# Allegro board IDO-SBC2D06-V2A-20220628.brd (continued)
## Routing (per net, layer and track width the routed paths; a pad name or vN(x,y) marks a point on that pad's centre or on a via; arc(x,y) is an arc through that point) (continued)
LCD_PWM: length 5
  TOP w0.203: J7.29 47.96,29.11 47.7,29.37 44.44,29.37 R70.2
LCD_RSTB: length 5.3
  TOP w0.203: J7.31 48.18,28.11 47.33,28.97 45.61,28.97 45.18,28.54 R71.2
LED0/PHYAD0: length 36.4
  TOP w0.203: v1(43.15,44.79) 42.82,45.12 R61.2 42.75,46.08 42.75,47.27 42.73,47.3 U5.11 ; v1(47.01,59.4) 47.01,66.38 48.15,67.53 R38.2
  BOTTOM w0.203: v1(43.15,44.79) 44.08,43.86 44.83,43.86 45.64,44.67 46.85,44.67 50,47.81 51.43,47.81 51.99,48.37 51.99,49.59 51.07,50.51 51.07,55.33 v1(47.01,59.4)
LED3/PHYAD3: length 34
  TOP w0.203: v1(44.55,45.25) 44.52,45.22 R62.1 43.33,45.78 43.33,46.39 43.15,46.57 43.15,47.39 43.13,47.41 U5.12 ; R36.2 47.01,67.53 46.25,66.76 v1(46.25,59.4)
  BOTTOM w0.203: v1(46.25,59.4) 46.25,59.34 50.67,54.92 50.67,50.28 51.58,49.36 51.58,48.6 51.2,48.22 49.83,48.22 46.65,45.05 44.75,45.05 v1(44.55,45.25)
LINEOUTL-: length 2
  TOP w0.305: C39.2 C42.2 R80.2
LINEOUTL_: length 3.9
  TOP w0.305: C39.1 41.01,11.7 D26.1 43.55,12.79 J8.3
LINEOUTR-: length 2.3
  TOP w0.305: C40.2 C41.2 R81.2
LINEOUTR_: length 6
  TOP w0.305: C40.1 46.33,7.63 D25.1 48.26,7.68 J8.2
MDI_RN: length 3.7
  TOP w0.203: R37.1 43.55,54.14 43.47,54.06 43.47,53.83 43.67,53.63 43.96,53.63 44.52,53.07 44.52,52.25 44.33,52.06 U5.26
MDI_RP: length 3.6
  TOP w0.203: U5.27 43.93,52.12 44.19,52.39 44.19,52.94 43.83,53.3 43.54,53.3 43.14,53.7 43.14,54.06 43.06,54.14 R34.1
MDI_RXN: length 4.7
  TOP w0.203: R37.2 43.49,55.47 43.49,55.91 D20.2 43.49,56.54 43.49,56.99 43.03,57.45 43.03,57.83 43.37,58.17 U4.12
MDI_RXP: length 4.7
  TOP w0.203: R34.2 43.16,55.47 43.16,55.91 D20.1 42.85,56.25 43.16,56.57 43.16,56.86 42.7,57.32 42.7,57.86 42.37,58.2 U4.11
MDI_TN: length 4.2
  TOP w0.203: U5.29 43.13,52.02 43.06,52.09 43.06,52.55 42.31,53.3 41.4,53.3 41.24,53.45 41.24,53.94 41.45,54.14 R33.1
MDI_TP: length 4.2
  TOP w0.203: R30.1 40.71,54.14 40.91,53.94 40.91,53.32 41.26,52.97 42.17,52.97 42.73,52.42 U5.30
MDI_TXN: length 5
  TOP w0.203: R33.2 41.21,55.47 41.21,55.91 D19.2 41.21,56.54 41.21,56.78 40.67,57.31 40.54,57.31 40.03,57.83 40.03,57.99 40.37,58.32 U4.9
MDI_TXP: length 5
  TOP w0.203: U4.8 39.37,58.32 39.7,57.99 39.7,57.69 40.41,56.98 40.53,56.98 40.88,56.64 40.88,56.57 40.56,56.25 D19.1 40.88,55.91 40.88,55.47 R30.2
NSD_CD: length 10.1
  BOTTOM w0.203: R17.2 33.75,44.39 35.17,44.39 35.5,44.71 R9.2 35.5,45.51 35.94,45.95 37.09,45.95 37.97,45.08 D12.1 38.56,44.45 J4.9
PANEL_B3: length 40.8
  TOP w0.203: v1(38.72,10.8) 38.5,10.58 38.08,10.58 37.92,10.74 37.92,11.03 R64.8 ; J7.16 49.55,35.61 49.88,35.95 50.07,35.95 v1(50.28,35.74)
  BOTTOM w0.203: v1(38.72,10.8) 38.48,10.56 38.28,10.56 37.94,10.89 37.94,15 36.64,16.3 36.64,16.72 36.85,16.92 37.54,16.92 37.74,17.13 37.74,17.53 37.54,17.74 36.85,17.74 36.64,17.94 36.64,24.32 39.79,27.47 43.87,27.47 45.45,29.04 47.04,29.04 48.29,30.3 48.29,31.89 48.68,32.28 48.68,34.9 49.73,35.95 50.07,35.95 v1(50.28,35.74)
PANEL_B4: length 41
  TOP w0.203: v1(50.96,35.41) 50.73,35.17 49.64,35.17 49.58,35.11 J7.17 ; R66.5 45.04,17.58 46.63,15.98 46.63,15.33 46.5,15.2 45.65,15.2 44.43,16.42 43.57,16.42 43.22,16.07 43.22,14.85 v1(42.93,14.57)
  BOTTOM w0.203: v1(42.93,14.57) 43.25,14.89 43.25,15.54 43.65,15.93 45.91,15.93 46.12,16.14 46.12,16.54 45.91,16.75 43.65,16.75 43.25,17.14 43.25,18.42 47.77,22.94 47.77,26.25 49,27.48 49,30.16 49,31.54 49.39,31.94 49.39,34.63 49.94,35.17 50.73,35.17 v1(50.96,35.41)
PANEL_B5: length 41.1
  TOP w0.203: v1(50.96,34.61) 50.73,34.84 49.78,34.84 49.55,34.61 J7.18 ; R66.6 44.95,18.13 46.96,16.12 46.96,15.19 46.64,14.87 45.51,14.87 44.29,16.09 43.71,16.09 43.55,15.93 43.55,14.85 v1(43.84,14.57)
  BOTTOM w0.203: v1(43.84,14.57) 43.58,14.82 43.58,15.4 43.78,15.6 46.05,15.6 46.45,16 46.45,16.68 46.05,17.08 43.78,17.08 43.58,17.28 43.58,18.29 48.1,22.81 48.1,26.11 49.33,27.34 49.33,30.3 49.33,31.4 49.72,31.8 49.72,34.49 50.07,34.84 50.73,34.84 v1(50.96,34.61)
PANEL_B6: length 40.6
  TOP w0.203: v1(45.99,18.46) 45.72,18.74 44.98,18.74 44.87,18.63 R66.7 ; v1(50.28,34.26) 50.04,34.03 49.59,34.03 49.51,34.11 J7.19
  BOTTOM w0.203: v1(50.28,34.26) 50.51,34.03 51.68,34.03 52.17,33.54 52.17,32.77 50.37,30.97 50.37,29.26 51.06,28.57 52.82,28.57 53.23,28.16 53.23,26.89 52.9,26.56 50.02,26.56 49.14,25.68 49.14,24.08 50.75,22.47 50.75,21.91 50.34,21.5 49.78,21.5 49.19,22.09 48.9,22.09 48.7,21.89 48.7,21.6 50.26,20.04 50.26,19.6 49.73,19.06 49.25,19.06 47.77,20.54 47.35,20.54 47.21,20.4 47.21,20.04 48.36,18.89 48.36,17.44 47.95,17.03 47.38,17.03 46.95,17.46 46.95,18.26 46.54,18.68 46.21,18.68 v1(45.99,18.46)
PANEL_B7: length 39.5
  TOP w0.203: J7.20 49.51,33.61 49.59,33.7 50.04,33.7 v1(50.28,33.46) ; R66.8 44.81,19.18 44.92,19.07 45.8,19.07 v1(45.99,19.27)
  BOTTOM w0.203: v1(50.28,33.46) 50.51,33.7 51.54,33.7 51.84,33.4 51.84,32.91 50.04,31.11 50.04,29.12 50.92,28.24 52.69,28.24 52.9,28.02 52.9,27.02 52.77,26.89 49.88,26.89 48.81,25.82 48.81,23.94 50.42,22.33 50.42,22.04 50.21,21.83 49.92,21.83 49.33,22.42 48.76,22.42 48.37,22.02 48.37,21.46 49.93,19.9 49.93,19.73 49.59,19.39 49.38,19.39 47.91,20.87 47.21,20.87 46.88,20.54 46.88,19.9 48.03,18.76 48.03,17.57 47.81,17.36 47.52,17.36 47.29,17.59 47.29,18.4 46.67,19.01 46.25,19.01 v1(45.99,19.27)
PANEL_DCLK: length 7.7
  TOP w0.203: R72.2 C38.2 44.37,30.7 v1(45.11,29.96) ; v1(47.63,32.87) 47.89,32.61 J7.22
  BOTTOM w0.203: v1(47.63,32.87) 45.11,30.36 v1(45.11,29.96)
PANEL_DE: length 8
  TOP w0.203: J7.27 47.28,30.11 45.77,31.63 45.77,33.4 45.74,33.43 45.74,33.67 R69.2
PANEL_G2: length 39.3
  TOP w0.203: R65.6 32.92,10 v1(32.91,9.99) ; J7.9 48.06,39.11 v1(45.36,36.41)
  BOTTOM w0.203: v1(32.91,9.99) 32.91,10.5 32.68,10.73 32.68,14.59 33.29,15.2 33.29,15.26 33.32,15.29 33.32,25.64 39.9,32.22 42.95,32.22 45.36,34.63 v1(45.36,36.41)
PANEL_G3: length 43
  TOP w0.203: R65.7 33.42,10.8 33.87,10.35 34.56,10.35 v1(34.77,10.14) ; J7.10 49.51,38.61 49.59,38.53 50.04,38.53 v1(50.28,38.76)
  BOTTOM w0.203: v1(34.77,10.14) 34.55,10.35 34.18,10.35 33.78,10.76 33.78,11.58 34.23,12.03 34.23,25.32 38.79,29.88 42.77,29.88 43.03,30.13 43.03,31.22 46.27,34.46 46.27,36.53 47.23,37.49 47.86,37.49 48.9,38.53 50.04,38.53 v1(50.28,38.76)
PANEL_G4: length 43.2
  TOP w0.203: v1(50.28,37.99) 50.07,38.2 49.59,38.2 49.51,38.11 J7.11 ; R65.8 33.85,11.03 33.85,10.83 34.01,10.68 34.5,10.68 v1(34.77,10.94)
  BOTTOM w0.203: v1(34.77,10.94) 34.51,10.68 34.32,10.68 34.11,10.89 34.11,11.44 34.76,12.1 35.52,12.1 35.71,12.28 35.71,12.66 35.46,12.91 34.76,12.91 34.56,13.11 34.56,25.18 38.93,29.55 42.91,29.55 43.36,30 43.36,31.08 46.6,34.32 46.6,36.39 47.36,37.16 48,37.16 49.04,38.2 50.07,38.2 v1(50.28,37.99)
PANEL_G5: length 41.1
  TOP w0.203: v1(36.3,10.24) 36.54,10.48 36.54,10.84 36.43,10.95 R64.5 ; J7.12 49.57,37.61 49.79,37.39 50.73,37.39 v1(50.96,37.63)
  BOTTOM w0.203: v1(50.96,37.63) 50.73,37.39 49.24,37.39 47.31,35.47 47.31,34.03 44.07,30.79 44.07,29.7 43.21,28.84 39.22,28.84 35.27,24.89 35.27,14.49 36.54,13.22 36.54,10.48 v1(36.3,10.24)
PANEL_G6: length 40.4
  TOP w0.203: R64.6 36.98,10.86 36.87,10.75 36.87,10.48 v1(37.11,10.24) ; v1(50.96,36.82) 50.73,37.06 49.66,37.06 49.61,37.11 J7.13
  BOTTOM w0.203: v1(50.96,36.82) 50.73,37.06 49.37,37.06 47.64,35.33 47.64,33.89 44.4,30.65 44.4,29.56 43.34,28.51 39.36,28.51 35.6,24.75 35.6,14.63 36.87,13.36 36.87,10.48 v1(37.11,10.24)
PANEL_G7: length 40.7
  TOP w0.203: J7.14 49.55,36.61 49.88,36.28 50.07,36.28 v1(50.28,36.49) ; v1(38.72,9.99) 38.47,10.25 37.94,10.25 37.59,10.6 37.59,10.74 37.48,10.85 R64.7
  BOTTOM w0.203: v1(38.72,9.99) 38.48,10.23 38.14,10.23 37.61,10.76 37.61,14.86 36.31,16.16 36.31,24.46 39.65,27.8 43.73,27.8 45.31,29.37 46.9,29.37 47.96,30.43 47.96,32.02 48.35,32.42 48.35,35.03 49.6,36.28 50.07,36.28 v1(50.28,36.49)
PANEL_HS: length 7.8
  TOP w0.203: R67.2 44.47,32.98 44.85,32.6 44.85,31.08 45.86,30.07 v1(45.86,29.96) ; v1(47.25,31.61) J7.24
  BOTTOM w0.203: v1(47.25,31.61) 47.23,31.61 45.86,30.25 v1(45.86,29.96)
PANEL_R3: length 45.1
  TOP w0.203: R63.5 26.53,10.46 v1(26.31,10.25) ; J7.3 47,42.11 44.85,39.97 v1(44.6,39.97)
  BOTTOM w0.203: v1(44.6,39.97) 42.82,38.19 42.82,35.27 41.83,34.28 38.97,34.28 26.44,21.75 26.44,10.38 v1(26.31,10.25)
PANEL_R4: length 45.1
  TOP w0.203: J7.4 47.13,41.61 v1(44.6,39.08) ; v1(26.94,9.74) 27.08,9.87 R63.6
  BOTTOM w0.203: v1(26.94,9.74) 26.94,21.68 39.14,33.87 42,33.87 43.3,35.18 43.3,37.78 v1(44.6,39.08)
PANEL_R5: length 43.2
  TOP w0.203: R63.7 27.58,10.38 v1(27.71,10.25) ; J7.5 47.52,41.11 v1(44.6,38.19)
  BOTTOM w0.203: v1(27.71,10.25) 27.45,10.5 27.45,21.56 39.33,33.44 42.14,33.44 43.71,35.01 43.71,37.3 v1(44.6,38.19)
PANEL_R6: length 44.2
  TOP w0.203: v1(28.09,9.49) 28.34,9.74 28.34,10.5 28.13,10.72 R63.8 ; J7.6 47.85,40.61 v1(44.57,37.33)
  BOTTOM w0.203: v1(44.57,37.33) 44.22,36.98 44.22,34.89 42.36,33.03 39.5,33.03 27.96,21.49 27.96,10.88 28.34,10.5 28.34,9.74 v1(28.09,9.49)
PANEL_R7: length 39.6
  TOP w0.203: J7.7 48.17,40.11 v1(45.36,37.3) ; v1(32.15,10.38) 32.37,10.59 R65.5
  BOTTOM w0.203: v1(45.36,37.3) 44.72,36.66 44.72,34.76 42.59,32.63 39.67,32.63 32.91,25.87 32.91,15.46 32.28,14.82 32.28,10.5 v1(32.15,10.38)
PANEL_VS: length 8.2
  TOP w0.203: v1(46.62,29.95) 46.62,30.03 45.36,31.28 45.36,33.24 44.47,34.12 R68.2 ; v1(47.37,30.85) 47.63,31.11 J7.25
  BOTTOM w0.203: v1(47.37,30.85) 46.62,30.1 v1(46.62,29.95)
PHY_AVDD33: length 0.7
  TOP w0.203: 42.18,52.29 42.33,52.14 U5.31
  vias: v1(38.88,53.43) v1(39.64,53.43) v1(44.72,53.94) v1(45.49,53.94)
PHY_DVDD33: length 26.9
  TOP w0.203: R55.1 37.94,47.43 38.79,46.58 40.77,46.58 41.44,45.91 41.44,45.64 43.68,43.4 46.25,43.4 46.63,43.78 46.63,45.17 v1(46.12,45.68) ; 44.08,46.18 43.53,46.73 U5.13
  TOP w0.381: 44.08,46.18 44.32,45.94 45.11,45.94 45.33,45.71 C32.2
  TOP w0.508: R59.1 v1(48.59,50) ; C32.2 45.66,45.22 46.12,45.68 v1(46.12,45.68) ; R60.1 v1(48.59,52.29)
  BOTTOM w0.508: v1(48.59,52.29) v1(48.59,50) ; 49.42,50 49.42,48.61 46.5,45.68 v1(46.12,45.68)
  vias: v1(48.66,53.94) v1(49.42,53.94)
PM_IRIN: length 53.5
  TOP w0.203: U2.23 12.96,17.84 13.66,18.53 18.21,18.53 19.92,20.24 19.92,25.17 16.43,28.66 16.43,33.15 v1(16.25,33.33)
  BOTTOM w0.203: 4.85,54.19 4.85,53.17 3.42,51.75 3.42,45.77 3.74,45.45 3.74,43.64 4.51,42.86 5,42.86 5.94,41.92 5.94,40.8 6.22,40.53 6.22,39.04 9.49,35.76 10.95,35.76 13.1,33.62 15.97,33.62 v1(16.25,33.33)
PM_LED0: length 32
  TOP w0.203: R31.1 28.72,62.95 30.88,60.79 v1(30.88,55.97) ; U2.78 33.48,44.55 32.23,45.8 32.23,50.27 33,51.04 34.54,51.04 35.39,51.88 35.71,51.88 36.16,52.34 v1(36.16,52.59)
  BOTTOM w0.203: v1(36.16,52.59) 36.16,52.72 35.83,53.05 32.85,53.05 30.88,55.02 v1(30.88,55.97)
PM_LED0_: length 22.1
  TOP w0.203: v1(29.61,62.95) 29.61,68.54 29.18,68.97 R31.2
  BOTTOM w0.203: J6.B12 38.12,71.35 38.12,68.29 32.79,62.95 v1(29.61,62.95)
PM_LED1: length 31.3
  TOP w0.203: v1(35.39,52.46) 34.38,51.45 32.83,51.45 31.77,50.39 31.77,45.47 32.38,44.86 U2.79 ; R29.1 28.21,67.48 28.21,62.83 30.25,60.79 v1(30.25,56.48)
  BOTTOM w0.203: v1(35.39,52.46) 35.21,52.64 32.68,52.64 30.25,55.08 v1(30.25,56.48)
PM_LED1_: length 4.4
  TOP w0.203: J6.B10 27.58,70.46 R29.2
PM_RESET: length 43.8
  TOP w0.203: SW1.3 42.84,4 41.17,5.68 D3.1 40.89,6.59 40.53,6.95 40.53,7.8 40.28,8.06 39.33,8.06 38.96,8.42 31.06,8.42 v1(30.88,8.6) ; U2.24 12.52,16.74 13.9,18.13 16.91,18.13 v1(17.81,17.23)
  BOTTOM w0.203: v1(17.81,17.23) 17.86,17.23 23,12.09 23.44,12.09 24.98,10.55 24.98,9.03 26.02,8 30.28,8 v1(30.88,8.6)
PM_UART_RX: length 43
  TOP w0.203: v1(23.9,10.76) 23.9,10.38 26.97,7.3 26.97,2.41 26.17,1.61 17.67,1.61 14.74,4.55 13.12,4.55 12.85,4.28 12.85,2.25 11.99,1.39 J11.4 ; U2.25 13.68,15.65 14.63,16.6 v1(15.9,16.6)
  BOTTOM w0.203: v1(15.9,16.6) 17.92,16.6 22.87,11.65 23.31,11.65 23.9,11.06 v1(23.9,10.76)
PM_UART_TX: length 38.5
  TOP w0.203: J11.3 11.86,4.18 12.64,4.96 14.96,4.96 17.93,1.99 25.8,1.99 26.56,2.76 26.56,7.07 23.13,10.5 v1(23.13,10.76) ; v1(15.26,15.96) 15.01,15.96 14.78,15.73 U2.26
  BOTTOM w0.203: v1(23.13,10.76) 17.93,15.96 v1(15.26,15.96)
REGOUT: length 2
  TOP w0.203: v1(43.63,52.69) 43.53,52.59 U5.28
  BOTTOM w0.508: v1(43.63,52.69) 43.66,52.72 R42.1
RMII_COL: length 4.1
  TOP w0.203: U5.4 40.66,49.82 40.66,49.81 40.15,49.81 39.73,49.4 39.73,49.06 39.32,48.65 39.32,48.1 38.8,47.59 R55.2
RMII_MDC: length 2.2
  TOP w0.203: U5.22 45.88,50.22 46.25,50.58 46.55,50.58 47.09,51.12 R41.2
RMII_MDIO: length 3.8
  TOP w0.203: U5.23 45.75,50.62 46.25,51.12 46.25,51.19 47.09,52.03 R60.2 R40.2
RMII_REF_CLK: length 37
  TOP w0.203: v1(45.61,47.56) 45.61,47.49 46.55,46.55 R52.1
  BOTTOM w0.203: R47.2 32.02,30.06 31.49,30.59 31.49,31.67 28.5,34.67 28.5,39.87 27.81,40.56 27.81,42.99 31.77,46.95 34.35,46.95 35.21,47.81 38.33,47.81 39.17,46.97 40.07,46.97 40.25,47.15 40.66,47.15 41.46,47.95 45.22,47.95 v1(45.61,47.56)
RMII_RST: length 7.1
  TOP w0.203: U5.32 39.68,51.62 39.39,51.9 C36.2 R57.2 38.8,50.73 38.29,50.22 37.49,50.22 37.36,50.35 36.93,50.35 R51.2
RMII_RX_D0: length 2.6
  TOP w0.203: U5.18 45.97,48.62 47.01,47.59 R44.2
RMII_RX_D1: length 3.2
  TOP w0.203: R45.2 47.75,46.49 47.35,46.89 47.07,46.89 45.74,48.22 U5.17
RMII_RX_DV: length 5.3
  TOP w0.203: U5.19 46.93,49.02 R58.2 47.09,48.4 47.34,48.15 49.22,48.15 49.5,48.43 R43.2
RMII_TX_D0: length 55.6
  TOP w0.203: v1(44.79,25.04) 44.47,24.73 R48.2 ; U5.9 40.54,47.62 v1(40.41,47.75) ; v1(27.92,39.59) 29.1,38.4 29.1,29.86 34.49,24.47 38.21,24.47 v1(38.43,24.25)
  BOTTOM w0.203: v1(44.79,25.04) 44.59,25.04 44.13,24.59 40.46,24.59 40.35,24.48 39.69,24.48 39.3,24.09 38.59,24.09 v1(38.43,24.25) ; v1(40.41,47.75) 40.41,47.76 39.42,48.74 39.42,49.71 37.63,51.51 37.07,51.51 36.51,50.95 32.66,50.95 30.04,48.33 30.04,46.56 26.62,43.14 26.62,40.88 v1(27.92,39.59)
RMII_TX_D1: length 56.1
  TOP w0.203: v1(27.86,38.83) 28.7,37.99 28.7,29.69 34.7,23.68 v1(37.93,23.68) ; R49.2 44.52,23.58 v1(44.78,23.84) ; v1(40.48,48.5) 40.77,48.22 U5.8
  BOTTOM w0.203: v1(40.48,48.5) 39.83,49.15 39.83,49.88 37.79,51.92 36.9,51.92 36.34,51.36 32.49,51.36 29.64,48.5 29.64,46.73 26.21,43.31 26.21,40.47 v1(27.86,38.83) ; v1(44.78,23.84) 44.71,23.77 40.8,23.77 40.2,23.18 38.44,23.18 v1(37.93,23.68)
RMII_TX_EN: length 58.2
  TOP w0.203: R50.2 v1(44.78,25.87) ; v1(40.55,49.26) 40.71,49.42 U5.5 ; v1(39.06,24.67) 39.06,23.99 38.17,23.1 34.71,23.1 28.21,29.6 28.21,37.65 v1(27.83,38.03)
  BOTTOM w0.203: v1(44.78,25.87) 44.78,25.85 43.92,24.99 40.29,24.99 40.18,24.88 39.27,24.88 v1(39.06,24.67) ; v1(40.55,49.26) 40.24,49.57 40.24,50.05 37.96,52.32 36.73,52.32 36.17,51.76 32.32,51.76 29.23,48.67 29.23,46.9 25.81,43.47 25.81,40.06 v1(27.83,38.03)
RST#: length 5.9
  TOP w0.203: J7.33 46.88,27.11 D22.1 46.86,27.29 45.95,28.2 R73.2 44.95,27.42 R79.2
RTC_VBAT: length 19.2
  TOP w0.508: J2.1 26.06,58.79 26.06,53.3 24.76,52.01 v1(16.94,52.01) ; D5.A v1(16.78,49.24)
  BOTTOM w0.508: v1(16.78,49.24) 16.94,49.39 v1(16.94,52.01)
SAR_GPIO2: length 44.6
  TOP w0.203: v1(15.53,32.99) 16.02,32.5 16.02,28.49 19.51,25 19.51,20.47 17.98,18.94 U2.22
  BOTTOM w0.203: v1(15.53,32.99) 13.09,32.99 10.82,35.27 9.41,35.27 5.81,38.87 5.81,39.89 5.35,40.35 4.34,40.35 3.83,40.86 3.83,42.97 3.33,43.47 3.33,45.29 2.31,46.31 2.31,46.57
SD_CDZ: length 22.6
  TOP w0.203: U2.67 39.72,36.54 38.62,35.44 38.62,34.49 37.37,33.24 v1(33.42,33.24)
  BOTTOM w0.203: v1(33.42,33.24) 32.8,33.24 30.53,35.51 30.53,42.12 32.26,43.85 R17.1
SD_CLK: length 14.5
  TOP w0.203: v1(32.69,36.69) 34.07,36.69 34.4,36.36 34.92,36.36 36.12,37.55 38.12,37.55 40.41,39.84 U2.70
  BOTTOM w0.203: R18.1 32.36,37.03 v1(32.69,36.69)
SD_CLK_: length 10.4
  BOTTOM w0.203: J4.5 38.9,40.05 D13.1 37.97,40.57 37.68,40.28 36.02,40.28 35.75,40.56 35.75,40.86 C14.2 35.42,41.02 35.42,40.73 35.1,40.41 33.83,40.41 33.22,41.03 R18.2
SD_CMD: length 8.9
  TOP w0.203: U2.71 40.65,40.94 37.99,38.29 35.99,38.29 v1(34.64,36.94)
  BOTTOM w0.203: R16.1 v1(34.64,36.94)
SD_CMD_: length 8.1
  BOTTOM w0.203: R16.2 R8.2 35.73,37.91 37.51,37.91 37.97,37.45 D11.1 39.44,37.22 40.07,37.85 J4.3
SD_D0: length 17.6
  TOP w0.203: U2.69 40.2,38.74 36.72,35.27 v1(32.66,35.27)
  BOTTOM w0.203: R10.1 31.75,41.77 31.75,36.18 v1(32.66,35.27)
SD_D0_: length 9.8
  BOTTOM w0.203: R10.2 33.52,42.38 34.15,43.01 35.2,43.01 35.5,42.71 R7.2 35.5,42.21 36.03,41.68 37.68,41.68 37.97,41.97 D7.1 39.01,42.38 39.14,42.25 J4.7
SD_D1: length 23.3
  TOP w0.203: U2.68 39.96,37.64 38.01,35.69 38.01,34.74 37.15,33.88 v1(32.98,33.88)
  BOTTOM w0.203: R11.1 33.93,43.65 33.26,42.99 32.08,42.99 31.14,42.05 31.14,35.77 32.98,33.92 v1(32.98,33.88)
SD_D1_: length 6.7
  BOTTOM w0.203: J4.8 40.33,43.35 40.03,43.65 D8.1 37.97,43.93 37.61,44.28 36.14,44.28 R11.2
SD_D2: length 15
  TOP w0.203: v1(33.17,38.32) 33.17,38.52 35.2,40.54 35.2,41.29 35.65,41.74 37.87,41.74 38.98,42.86 U2.73
  BOTTOM w0.203: R13.1 34.5,33.49 33.27,34.71 33.27,38.23 v1(33.17,38.32)
SD_D2_: length 7.2
  BOTTOM w0.203: J4.1 40.28,35.65 40.03,35.9 39.08,35.9 37.84,34.66 D9.1 37.84,34.22 37.1,33.49 R13.2
SD_D3: length 12.8
  TOP w0.203: U2.72 39.94,42.04 38.12,40.22 35.76,40.22 33.93,38.38 v1(33.93,38.34)
  BOTTOM w0.203: v1(33.93,38.34) 33.88,38.3 33.88,35.39 R15.1
SD_D3_: length 7
  BOTTOM w0.203: R15.2 35.5,34.89 36,35.39 37.49,35.39 37.97,35.87 D10.1 38.25,36.16 38.63,36.54 39.9,36.54 40.11,36.75 J4.2
SOM_3V3: length 3.3
  TOP w0.508: C10.2 C9.2 13.17,49.25 13.17,50.97 L2.2
SYS_3V3: length 145.7
  TOP w0.254: J6.A12 48.92,68.68 48.92,67.14 47.65,65.87 47.65,56.86
  TOP w0.305: J7.38 49.82,24.61 v1(50.19,24.98)
  TOP w0.381: R61.1 41.96,46.06 40.94,47.08 40.15,47.08 v1(39.64,47.59) ; 18.31,50 18.31,48.6 17.51,47.8 D4.A ; v1(37.31,50.93) 37.78,50.93 R57.1 ; v1(17.04,56.98) 17.04,60.03 10.94,66.13 R89.1 ; C4.2 R3.1 18.61,11.69 17.42,10.5 11.9,10.5 C5.2
  TOP w0.508: v1(29.87,30.71) 29.87,31.35 30.88,32.37 30.88,36.41 32.06,37.59 34.21,37.59 v1(34.97,38.34) ; R73.1 46.9,28.41 v1(47.62,27.69) ; v1(37.57,52.9) 37.23,52.56 37.23,51.01 v1(37.31,50.93) ; v1(34,41.87) v1(29.81,41.87) 28.15,41.87 26.39,40.11 26.39,35.47 26.53,35.33 v1(26.53,32.98) ; v1(45.23,22.47) 45.92,22.47 R75.1 ; R82.1 38.5,7.84 38.88,7.45 v1(39.14,7.45) R1.1 ; v1(42.64,21.3) R74.1
  TOP w0.711: J12.1 4.85,9.41 ; J12.1 5.79,8.47 ; J12.1 3.91,8.47 ; J12.17 5.79,28.79 ; J12.17 4.85,29.73 ; J12.17 4.85,27.85
  BOTTOM w0.381: R7.1 34.13,41.87 v1(34,41.87)
  BOTTOM w0.406: v1(29.81,41.87) 29.82,41.88 29.82,42.35 32.52,45.05 R9.1
  BOTTOM w0.508: v1(17.04,56.98) 17.04,53.56 17.72,52.87 v1(17.72,51.14) ; v1(37.57,52.9) 37.57,53.39 38.88,54.7 42.44,54.7 43.07,55.33 44.85,55.33 46.25,56.73 v1(46.25,56.98) ; R8.1 34.64,38.02 v1(34.97,38.34) ; 41.8,9.87 41.7,9.97 41.7,18.52 43.2,20.03 43.2,20.74 v1(42.64,21.3) 43.81,22.47 v1(45.23,22.47) 45.69,22.47 46.76,23.53 46.76,26.83 v1(47.62,27.69) ; v1(39.64,47.59) 38.76,48.48 38.76,49.49 37.32,50.93 v1(37.31,50.93) ; 26.18,30.31 28.09,30.31 28.48,30.71 v1(29.87,30.71)
  vias: v1(8.91,8.72) v1(9.67,8.72) v1(9.89,15.05) v1(10.05,15.71) v1(10.05,9.36) v1(10.43,8.72) v1(10.69,15.33) v1(11.2,8.72) v1(11.45,15.33) v1(21.1,41.74) v1(21.1,40.98) v1(21.86,41.74) v1(21.86,40.98) v1(23.64,48.6) v1(23.64,47.84) v1(23.64,47.08) v1(23.64,46.32) v1(24.56,34.54) v1(24.56,32.06) v1(24.56,31.36) v1(50.44,25.62) v1(50.95,24.98)
TF_3V3: length 12.8
  TOP w0.508: v1(27.62,37.05) 27.1,37.56 27.1,39.82 27.6,40.32 32.85,40.32 v1(32.95,40.22)
  BOTTOM w0.508: Q1.3 26.82,37.62 C17.2 26.98,37.68 v1(27.62,37.05) ; v1(32.95,40.22) 33.53,39.63 L3.1
TP_SCL: length 10.4
  TOP w0.203: J7.36 48.12,25.61 47.87,25.36 47.87,21.8 D23.1 46.86,21.07 46.45,21.48 44.32,21.48 R74.2 R77.2
TP_SDA: length 8.3
  TOP w0.203: R76.2 44.69,21.89 46.58,21.89 46.81,22.11 R75.2 46.86,22.49 D24.1 47.46,24.19 47.46,25.53 48.05,26.11 J7.35
TTL0: length 2.8
  TOP w0.203: R63.4 26.53,12.95 25.78,13.7 U2.36
TTL1: length 2.6
  TOP w0.203: R63.3 27.07,12.15 27.07,13.3 26.88,13.49 U2.37
TTL2: length 2.7
  TOP w0.203: R63.2 27.58,12.15 27.58,13.17 27.98,13.57 U2.38
TTL3: length 2.9
  TOP w0.203: R63.1 28.13,12.83 29.08,13.78 U2.39
TTL4: length 4
  TOP w0.203: R65.4 32.37,12.57 32.15,12.79 31.14,12.79 30.18,13.75 U2.40
TTL5: length 3.6
  TOP w0.203: U2.41 31.28,13.54 31.64,13.17 32.41,13.17 32.92,12.66 R65.3
TTL6/MIPI_TX_D0P: length 2.8
  TOP w0.203: U2.43 33.48,14.01 33.86,13.62 33.86,13.23 33.53,12.89 33.53,12.54 33.42,12.43 R65.2
TTL7/MIPI_TX_D0N: length 2.8
  TOP w0.203: R65.1 33.97,12.15 33.97,12.43 33.86,12.54 33.86,12.76 34.19,13.09 34.19,13.63 34.58,14.02 U2.44
TTL8/MIPI_TX_D1P: length 2.9
  TOP w0.203: R64.4 36.43,12.43 36.54,12.54 36.54,12.78 36.06,13.26 36.06,13.62 35.68,14.01 U2.45
TTL9/MIPI_TX_D1N: length 2.9
  TOP w0.203: U2.46 36.78,14.02 36.39,13.63 36.39,13.4 36.87,12.92 36.87,12.54 36.98,12.43 R64.3
TTL10/MIPI_TX_CKP: length 3
  TOP w0.203: R64.2 37.48,12.43 37.59,12.54 37.59,12.88 38.26,13.55 38.26,13.71 37.88,14.1 U2.47
TTL11/MIPI_TX_CKN: length 3
  TOP w0.203: U2.48 38.98,14.09 38.59,13.71 38.59,13.41 37.92,12.74 37.92,12.48 38.03,12.37 38.03,12.15 R64.1
TTL12/MIPI_TX_D2P: length 2.9
  TOP w0.203: R66.4 43.34,17.58 43.23,17.69 42.89,17.69 42.33,17.13 41.95,17.13 41.57,16.74 U2.49
TTL13/MIPI_TX_D2N: length 2.9
  TOP w0.203: U2.50 41.58,17.84 41.96,17.46 42.19,17.46 42.75,18.02 43.2,18.02 43.31,18.13 R66.3
TTL14/MIPI_TX_D3P: length 3
  TOP w0.203: R66.2 43.31,18.63 43.2,18.74 42.79,18.74 42.2,19.33 41.91,19.33 41.53,18.94 U2.51
TTL15/MIPI_TX_D3N: length 3
  TOP w0.203: R66.1 43.37,19.18 43.26,19.07 42.93,19.07 42.34,19.66 41.92,19.66 41.54,20.04 U2.52
TTL16: length 44
  TOP w0.203: U2.54 40.35,22.24 39.9,22.7 34.54,22.7 25.95,31.29 25.95,35.12 25.83,35.24 25.83,40.34 27.2,41.71 v1(27.2,42) ; v1(34.82,50.29) 35.29,50.76 R51.1
  BOTTOM w0.203: v1(27.2,42) 27.2,43.14 30.45,46.39 30.45,48.17 32.57,50.29 v1(34.82,50.29)
TTL17: length 2.3
  TOP w0.203: R49.1 43.04,23.34 U2.55
TTL18: length 2.3
  TOP w0.203: U2.56 42.99,24.44 R48.1
TTL19: length 2.9
  TOP w0.203: U2.57 41.58,25.54 42.13,24.99 42.66,24.99 43.28,25.62 R50.1
TTL20: length 9.7
  TOP w0.203: v1(33.6,30.31) 36.78,27.13 40.03,27.13 40.52,26.64 U2.58
  BOTTOM w0.203: R47.1 33.35,30.06 v1(33.6,30.31)
TTL21: length 61.1
  TOP w0.203: v1(33.42,31.08) 33.93,31.08 37.26,27.74 U2.59 ; R43.1 v1(51,48.86)
  BOTTOM w0.203: v1(33.42,31.08) 32.79,31.08 28.98,34.89 28.98,40.09 28.34,40.73 28.34,42.74 32.05,46.44 34.56,46.44 35.45,47.33 37.99,47.33 38.88,46.44 40.15,46.44 40.41,46.7 40.91,46.7 41.68,47.46 44.72,47.46 45.23,46.95 45.87,46.95 47.65,48.73 47.65,54.44 47.9,54.7 49.8,54.7 50.06,54.44 50.06,49.8 v1(51,48.86)
TTL22: length 49.1
  TOP w0.203: U2.60 37.05,28.84 v1(34.18,31.71) ; R44.1 48.33,44.08 46.76,42.51 43.28,42.51 39.72,46.06 38.37,46.06 v1(37.82,46.62)
  BOTTOM w0.203: v1(34.18,31.71) 32.89,31.71 29.51,35.09 29.51,40.29 28.83,40.98 28.83,42.65 32.17,45.99 34.83,45.99 35.6,46.76 37.67,46.76 v1(37.82,46.62)
TTL23: length 44.3
  TOP w0.203: R45.1 47.77,44.28 46.48,42.99 43.55,42.99 43.3,43.24 40.72,45.82 v1(40.72,45.85) ; U2.61 36.97,29.94 v1(34.95,31.97)
  BOTTOM w0.203: v1(40.72,45.85) 37.77,45.85 37.26,46.36 35.77,46.36 35,45.59 32.34,45.59 29.23,42.48 29.23,41.15 29.92,40.46 29.92,35.26 32.83,32.35 34.56,32.35 v1(34.95,31.97)
TTL24/LCD_PCLK: length 2.5
  TOP w0.203: R72.1 42.54,31.84 41.74,31.04 U2.62
TTL25/LCD_HSYNC: length 2.5
  TOP w0.203: U2.63 41.98,32.14 42.82,32.98 R67.1
TTL26/LCD_VSYNC: length 2.6
  TOP w0.203: R68.1 42.82,34.12 41.94,33.24 U2.64
TTL27/LCD_DE: length 2.6
  TOP w0.203: U2.65 42.02,34.34 42.95,35.27 R69.1
UART0_RX: length 94.3
  TOP w0.203: v1(25.6,12.66) 25.6,9.94 27.86,7.68 27.86,2.02 26.69,0.85 17.04,0.85 16.5,1.39 J11.2 ; D30.A 3.97,66.13 R89.2 5.43,66.05 5.99,65.49 10.82,65.49 16.4,59.91 16.4,56.68 17.13,55.95 v1(17.77,55.95) ; v1(17.9,37.08) 17.98,37.08 18.5,36.56 18.5,36.07 19.27,35.3 19.27,29.83 22.76,26.35 22.76,19.77 23.52,19.02 v1(23.52,18.88)
  BOTTOM w0.203: v1(17.9,37.08) 17.72,37.25 17.72,40.66 19.17,42.11 19.17,46.99 19.48,47.3 19.48,53.08 18.74,53.82 18.74,54.56 17.77,55.53 v1(17.77,55.95) ; v1(23.52,18.88) 23.52,15.2 25.6,13.12 v1(25.6,12.66)
UART0_RX_: length 24.2
  TOP w0.203: v1(10.94,4.66) 11.81,5.52 15.54,5.52 16.94,4.13 22.14,4.13 J10.3 ; J11.6 9.86,1.42 8.4,2.88 8.4,6.57 8.56,6.72 D29.1 v1(9.04,4.66)
  BOTTOM w0.203: v1(10.94,4.66) v1(9.04,4.66)
UART0_TX: length 94.1
  TOP w0.203: v1(24.9,12.95) 24.9,10 27.45,7.45 27.45,2.19 26.5,1.23 17.29,1.23 15.13,3.39 J11.1 ; v1(18.31,56.91) 17.55,57.67 17.55,60.29 11.07,66.76 5.61,66.76 5.35,67.02 R88.1 ; v1(17.92,36.32) 17.92,36.08 18.87,35.13 18.87,29.67 22.36,26.18 22.36,19.36 v1(22.7,19.01)
  BOTTOM w0.203: v1(24.9,12.95) 24.9,13 22.94,14.96 22.94,18.78 v1(22.7,19.01) ; v1(18.31,56.91) 18.44,56.78 18.44,55.44 19.14,54.73 19.14,53.99 19.89,53.25 19.89,47.13 19.58,46.82 19.58,41.94 18.48,40.84 18.48,36.67 18.12,36.32 v1(17.92,36.32)
UART0_TX_: length 20.4
  TOP w0.203: J11.5 9.86,6.44 10.15,6.72 D28.1 10.31,6.31 10.69,5.93 15.71,5.93 17.1,4.53 23.77,4.53 J10.4
UART1_RX: length 28.8
  TOP w0.203: J12.18 2.31,28.66 3.83,27.14 3.83,23.08 4.47,22.44 5.23,22.44 6.78,20.89 6.78,15.43 8.78,13.42 17.67,13.42 18.08,13.83 U2.29
UART1_TX: length 29.2
  TOP w0.203: J12.16 3.32,25.23 3.32,22.95 3.7,22.57 3.7,20.66 4.34,20.03 5.1,20.03 5.96,19.16 5.96,14.72 8.42,12.26 13.85,12.26 14.37,12.79 18.18,12.79 19.18,13.78 U2.30
UD+: length 9.4
  TOP w0.203: 5.99,79.82 5.99,78.79 6.14,78.65 6.14,77.75 D2.1 6.06,77.15 6.16,77.05 6.16,73.53 5.92,73.29 5.29,73.29 5.14,73.44 5.14,73.66 5.21,73.73 U6.1
UD-: length 10.5
  TOP w0.203: 6.64,79.82 6.64,78.79 6.49,78.65 6.49,77.79 D1.1 6.67,77.15 6.52,77 6.52,73.39 6.07,72.94 5.14,72.94 4.78,73.3 4.78,73.66 4.71,73.73 U6.2
USB-DRVVBUS: length 57.5
  TOP w0.203: U3.4 17.52,67.86 R123.1 16.28,66.89 20.34,62.83 20.34,58.76 22.5,56.6 22.5,55.46 21.61,54.57 v1(17.9,54.57) ; v1(9.04,28.03) 9.04,27.65 9.37,27.32 R19.2
  BOTTOM w0.203: v1(9.04,28.03) 9.04,30.44 10.43,31.84 16.28,31.84 17.32,32.88 17.32,40.83 18.59,42.1 18.59,46.99 19.07,47.47 19.07,52.91 17.9,54.08 v1(17.9,54.57)
USB_VBUS: length 1.6
  TOP w0.711: 17.36,76.18 J5.1 18.17,76.99
WIFI_ANT: length 4.3
  TOP w0.508: R6.1 C11.2 9.04,41 arc(9.09,40.72) 9.25,40.48 9.27,40.46 arc(9.96,40) 10.77,39.84 U2.3
WIFI_ANT_: length 4
  TOP w0.508: J3.2 D6.1 C12.2 R6.2
N992055: length 7.7
  BOTTOM w0.508: J4.4 38.57,38.95 C13.2 38.19,38.89 37.75,38.45 35.92,38.45 35.04,39.33 L3.2
N1029242: length 4
  TOP w0.381: R3.2 C4.1 R5.1 21.1,9.21 U1.5
N1030799: length 27.9
  TOP w0.203: v1(10.22,22.24) 9.93,21.95 R21.2
  BOTTOM w0.203: Q1.1 27.77,34.57 27.07,35.27 24.28,35.27 23.72,34.71 C16.1 R20.2 23.72,30.65 20.34,27.27 13.86,27.27 10.22,23.62 v1(10.22,22.24)
N6892349: length 1.5
  TOP w0.305: U3.3 17.64,70.88 R22.1
N11463456: length 2.4
  TOP w0.254: R4.2 21.45,47.84 20.51,46.9 LED2.A
N11537825: length 1.3
  TOP w0.305: R83.1 R82.2
N11641260: length 1.4
  TOP w0.254: LED1.A 21.94,48.68 R2.2
N11726744: length 2.2
  TOP w0.203: J6.A4 45.36,78.06 J6.A5
N11726756: length 2.2
  TOP w0.203: J6.A7 49.44,78.06 J6.A8
N11730936: length 1.6
  TOP w0.203: R46.1 45.18,52.36 44.73,51.91 U5.25
N11731046: length 4.3
  TOP w0.203: XT1.3 35.54,47.17 35.71,47.33 36.22,47.33 36.42,47.13 C37.2 R53.2 37.15,48.48 R54.1
N11735014: length 10.4
  TOP w0.508: U4.21 35.37,67.05 35.33,67.01 v1(35.33,67.01)
  BOTTOM w0.508: R28.1 28.69,64 28.98,63.72 32.53,63.72 35.33,66.52 v1(35.33,67.01)
N11735018: length 1.8
  BOTTOM w0.508: C23.2 28.09,65.87 27.49,65.27 R28.2
N11735022: length 1.8
  BOTTOM w0.508: R24.2 30.03,65.4 30.63,66 C21.2
N11735030: length 4.4
  TOP w0.508: U4.24 v1(32.37,67.01)
  BOTTOM w0.508: v1(32.37,67.01) 32.37,65.33 31.77,64.73 R24.1
N11735054: length 6.2
  TOP w0.508: U4.18 v1(38.37,67.01)
  BOTTOM w0.508: R32.1 39.85,65.53 v1(38.37,67.01)
N11735058: length 1.9
  BOTTOM w0.508: C25.2 43.84,66.13 43.24,66.73 R32.2
N11735062: length 1.9
  BOTTOM w0.508: R35.2 43.24,69.27 43.84,68.67 C27.2
N11735070: length 3.4
  TOP w0.508: U4.15 41.37,67.06 v1(41.42,67.01)
  BOTTOM w0.508: R35.1 41.84,68.07 41.42,67.65 v1(41.42,67.01)
N11735786: length 2.4
  TOP w0.508: U4.1 v1(32.37,57.58)
  BOTTOM w0.508: v1(32.37,57.58) 32.41,57.54 C20.1
N11735790: length 2.4
  TOP w0.508: U4.4 v1(35.37,57.59)
  BOTTOM w0.508: v1(35.37,57.59) 35.45,57.5 C22.1
N11735890: length 2.4
  TOP w0.508: U4.7 v1(38.37,57.59)
  BOTTOM w0.508: C24.1 38.5,57.45 v1(38.37,57.59)
N11735894: length 2.7
  TOP w0.508: U4.10 41.37,57.93 41.53,57.76 v1(41.53,57.59)
  BOTTOM w0.508: v1(41.53,57.59) 42.18,56.94 C26.1
N11746324: length 2.2
  TOP w0.203: J6.B5 30.63,78.32 J6.B4
N11746339: length 2.2
  TOP w0.203: J6.B7 33.69,78.06 J6.B8
N11786183: length 2.3
  TOP w0.203: U6.10 5.21,69.5 C48.2
N11786289: length 2.1
  TOP w0.203: R88.2 4.71,68.85 U6.9
N11786293: length 2.2
  TOP w0.203: U6.8 4.21,68.17 D30.C
N11791074: length 9.2
  TOP w0.203: R1.2 39.9,6.31 45.21,1 SW1.1
N11830519: length 21.4
  TOP w0.203: v1(45.36,64.73) 45.36,67.78 46.55,68.97 R36.1
  BOTTOM w0.203: v1(45.36,64.73) 39.64,64.73 37.74,66.64 37.74,67.27 38.53,68.06 38.53,70.6 40.42,72.49 J6.A10
N11830523: length 4.6
  TOP w0.203: J6.A11 50.44,70.95 48.46,68.97 R38.1

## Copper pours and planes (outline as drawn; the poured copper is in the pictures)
GND on TOP: 0.51,82.5 1.09,83.91 2.5,84.49 53.5,84.49 54.91,83.91 55.49,82.5 55.49,2.5 54.91,1.09 53.5,0.51 2.5,0.51 1.09,1.09 0.51,2.5 ; 36 cut-outs
GND on BOTTOM: 0.51,82.5 1.09,83.91 2.5,84.49 53.5,84.49 54.91,83.91 55.49,82.5 55.49,2.5 54.91,1.09 53.5,0.51 2.5,0.51 1.09,1.09 0.51,2.5 ; 14 cut-outs
GND_EARTH on TOP (solid shape): 2.81,64.6 4.85,64.6 6.62,62.83 6.62,59.27 5.86,58.51 1.04,58.51 0.53,59.02 0.53,65.62 0.66,65.75 1.67,65.75
GND_EARTH on TOP (solid shape): 55.49,79.36 55.49,59.37 54.63,58.51 51.2,58.51 49.42,60.29 49.42,62.95 54.38,67.91 54.38,75.91 52.22,78.07 52.22,79.34 52.34,79.46 55.39,79.46
GND_EARTH on BOTTOM (solid shape): 2.81,64.6 4.85,64.6 6.62,62.83 6.62,59.27 5.86,58.51 1.04,58.51 0.53,59.02 0.53,65.62 0.66,65.75 1.67,65.75
GND_EARTH on BOTTOM (solid shape): 55.49,66.54 55.49,59.37 54.63,58.51 51.2,58.51 49.55,60.16 49.42,60.16 48.79,60.79 48.79,65.37 50.31,66.89 55.14,66.89
GND_EARTH on TOP: 0.51,82.5 1.09,83.91 2.5,84.49 53.5,84.49 54.91,83.91 55.49,82.5 55.49,59.4 54.6,58.51 51.2,58.51 49.42,60.29 49.42,62.95 54.38,67.91 54.38,75.91 47.65,82.64 28.21,82.64 22.37,76.8 21.48,76.8 19.96,78.32 12.34,78.32 11.07,79.59 8.28,79.59 7.89,79.97 7.89,81.11 7.77,81.24 4.21,81.24 4.08,81.11 4.08,79.97 1.67,77.56 1.67,65.75 2.81,64.6 4.85,64.6 6.62,62.83 6.62,59.27 5.86,58.51 1.02,58.51 0.51,59.02 ; 4 cut-outs
GND_EARTH on BOTTOM: 0.51,82.5 1.09,83.91 2.5,84.49 53.5,84.49 54.91,83.91 55.49,82.5 55.49,59.37 54.63,58.51 51.2,58.51 49.55,60.16 45.61,60.16 45.49,60.29 45.49,62.06 46.63,63.21 46.63,69.56 46.76,69.68 53.87,69.68 54.38,70.19 54.38,75.91 47.65,82.64 28.21,82.64 24.4,78.83 24.4,77.3 31.64,70.07 31.64,68.54 31.52,68.41 27.33,68.41 27.2,68.54 27.2,72.61 23.01,76.8 21.48,76.8 19.96,78.32 12.34,78.32 11.07,79.59 8.28,79.59 7.89,79.97 7.89,81.11 7.77,81.24 4.21,81.24 4.08,81.11 4.08,79.97 1.67,77.56 1.67,65.75 2.81,64.6 4.85,64.6 6.62,62.83 6.62,59.27 5.86,58.51 1.04,58.51 0.51,59.04 ; 3 cut-outs
VCC5V on TOP: 21.61,68.54 21.61,66.13 21.48,66 19.83,66 19.2,66.64 19.2,68.54 19.32,68.67 21.48,68.67
VCC5V on TOP: 11.58,72.22 8.15,72.22 7.77,72.61 7.77,77.69 7.01,78.45 7.01,80.61 7.13,80.73 7.51,80.73 7.64,80.61 7.64,79.46 8.15,78.96 10.82,78.96 11.96,77.81 11.96,72.61
VCC5V on TOP: 23.77,8.09 24.02,7.84 24.02,6.06 22.88,4.91 20.09,4.91 19.96,5.04 19.96,7.96 20.09,8.09
VCC5V on TOP: 48.28,24.35 52.98,24.35 53.23,24.09 53.23,23.33 52.98,23.08 48.41,23.08 48.15,23.33 48.15,24.22
VCC5V on BOTTOM: 6.37,7.07 7.13,6.31 13.61,6.31 15.64,4.28 43.58,4.28 54,14.69 54,23.33 53.36,23.96 52.09,23.96 51.96,23.84 51.96,23.46 52.47,22.95 52.47,15.33 42.95,5.8 16.4,5.8 13.99,8.22 8.53,8.22 8.28,8.47 8.28,12.03 9.29,13.04 9.29,15.96 9.93,16.6 9.93,21.68 9.67,21.93 9.67,23.58 13.36,27.27 19.58,27.27 22.25,29.93 22.25,36.54 24.66,38.95 24.66,43.52 28.34,47.21 28.34,61.3 22.12,67.53 15.26,67.53 11.96,70.83 11.96,74.64 11.83,74.76 8.28,74.76 8.02,74.51 8.02,69.3 15.39,61.94 22.12,61.94 25.67,58.38 25.67,47.33 22.5,44.16 22.5,40.73 19.58,37.81 19.58,32.47 17.55,30.44 11.96,30.44 6.88,25.36 6.88,13.42 5.86,12.41 1.93,12.41 1.67,12.15 1.67,7.45 2.05,7.07
PHY_AVDD33 on TOP: 47.39,55.33 44.6,55.33 44.47,55.21 44.47,53.81 44.6,53.68 46.25,53.68 46.63,54.06 47.39,54.06 47.52,54.19 47.52,55.21
PHY_AVDD33 on TOP: 38.76,54.44 39.77,54.44 39.9,54.32 39.9,53.56 40.79,52.67 42.06,52.67 42.44,52.29 42.44,51.4 42.31,51.27 42.18,51.4 42.18,51.9 41.93,52.16 39.64,52.16 38.63,53.17 38.63,54.32
PHY_AVDD33 on BOTTOM: 38.88,54.06 42.57,54.06 43.2,54.7 45.61,54.7 45.74,54.57 45.74,53.3 45.61,53.17 43.45,53.17 42.82,52.54 39.26,52.54 38.63,53.17 38.63,53.81
PHY_DVDD33 on TOP: 50.44,55.33 50.57,55.21 50.57,53.81 50.44,53.68 48.53,53.68 48.03,54.19 48.03,55.21 48.15,55.33
PHY_DVDD33 on BOTTOM: 49.8,54.19 49.8,49.87 49.68,49.75 48.15,49.75 48.03,49.87 48.03,54.19 48.15,54.32 49.68,54.32
SOM_3V3 on TOP: 12.47,41.74 10.69,41.74 10.56,41.87 10.56,45.43 12.09,46.95 12.09,51.52 12.21,51.65 13.48,51.65 13.61,51.52 13.61,47.21 13.74,47.08 13.74,45.81 13.48,45.55 13.1,45.55 12.21,44.67 12.21,42.89 12.59,42.51 12.59,41.87
SYS_3V3 on TOP: 3.7,27.77 3.7,29.3 4.59,30.19 5.61,30.19 7.32,28.47 7.32,25.68 9.42,23.58 9.42,17.36 10.56,16.22 11.58,16.22 11.7,16.09 11.7,14.95 11.45,14.69 9.55,14.69 8.02,16.22 8.02,22.95 5.86,25.11 5.86,26.76 5.35,27.27 4.21,27.27
SYS_3V3 on TOP: 14.24,51.78 16.66,51.78 16.78,51.65 22.37,51.65 24.28,49.75 24.28,46.06 24.15,45.94 23.39,45.94 23.26,46.06 23.26,46.95 22.63,47.59 22.63,49.24 22.37,49.49 18.31,49.49 18.05,49.75 15.26,49.75 14.63,50.38 14.12,50.38 13.99,50.51 13.99,51.52
SYS_3V3 on TOP: 48.28,25.36 49.55,25.36 50.19,26 51.07,26 53.36,28.28 53.36,54.19 51.84,55.71 46.12,55.71 45.99,55.84 45.99,57.11 46.12,57.24 47.65,57.24 48.03,56.86 52.47,56.86 54.38,54.95 54.38,27.39 51.46,24.47 48.28,24.47 48.15,24.6 48.15,25.23
SYS_3V3 on TOP: 23.39,37.17 23.39,31.97 24.4,30.95 24.66,30.95 24.91,31.2 24.91,40.6 23.39,42.13 20.98,42.13 20.85,42 20.85,40.6 23.39,38.06
SYS_3V3 on TOP: 3.96,9.99 13.86,9.99 14.24,9.61 14.24,6.57 14.12,6.44 11.2,6.44 11.07,6.57 11.07,8.09 10.82,8.34 6.88,8.34 6.24,7.71 3.7,7.71 3.58,7.84 3.58,9.61
SYS_3V3 on BOTTOM: 22.63,48.98 24.15,48.98 24.53,48.6 24.53,46.57 22.25,44.28 22.25,40.86 22.12,40.73 20.98,40.73 20.85,40.86 20.85,45.3 22.63,47.08 22.63,47.33 22.5,47.46 22.5,48.86
SYS_3V3 on BOTTOM: 51.46,24.98 51.46,25.62 51.07,26 50.31,26 49.8,25.49 49.8,24.09 50.82,23.08 50.82,17.87 47.65,14.69 45.99,14.69 38.88,7.58 17.67,7.58 14.75,10.5 11.96,10.5 11.58,10.88 11.58,12.28 12.72,13.42 12.72,22.06 13.48,22.82 13.48,23.2 14.88,24.6 22.75,24.6 26.56,28.41 26.56,32.6 27.2,33.24 27.2,34.76 26.94,35.01 24.53,35.01 24.28,34.76 24.28,30.57 20.59,26.89 14.24,26.89 10.82,23.46 10.82,22.06 10.43,21.68 10.43,16.6 9.55,15.71 9.55,12.66 8.53,11.65 8.53,8.6 8.66,8.47 14.12,8.47 16.53,6.06 42.69,6.06 52.22,15.58 52.22,22.82 51.71,23.33 51.71,24.73
UART0_TX on TOP (solid shape): 15.21,3.45 15.23,3.39 15.21,3.33 14.56,2.69 13.84,3.39 14.56,4.09
USB_VBUS on TOP: 17.04,77.81 19.45,77.81 21.23,76.03 21.23,70.32 20.98,70.07 19.45,70.07 19.32,70.19 19.32,71.84 18.82,72.35 18.82,74.64 18.44,75.02 17.17,75.02 16.78,75.4 16.78,77.56
N1029238 on TOP: 16.91,9.87 16.91,7.84 17.17,7.58 18.82,7.58 18.94,7.45 18.94,6.57 18.82,6.44 14.88,6.44 14.75,6.57 14.75,9.74 15.01,9.99 16.78,9.99
N11537825 on TOP: 37.36,8.09 35.58,8.09 35.45,7.96 35.45,7.58 35.96,7.07 35.96,6.06 36.09,5.93 37.74,5.93 37.87,6.06 37.87,6.95 37.36,7.45
N11730332 on BOTTOM: 45.87,52.67 45.87,52.16 44.98,51.27 42.82,51.27 42.69,51.4 42.69,52.16 42.82,52.29 44.85,52.29 45.36,52.79 45.74,52.79

Small or netless copper shapes (teardrops, artwork), in the pictures only: 123 on TOP, 13 on BOTTOM

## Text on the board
Ref Des/Silkscreen Bottom: NC | GND | GPIO5 | VCC5V | GPIO89 | GPIO88 | GPIO87 | GPIO73 | GPIO49 | GPIO50 | SPI CS0 | VCC3V3 | GPIO59 | GPIO18 | GPIO17 | GPIO15 | GPIO16 | GPIO47 | GPIO12 | GPIO13 | GPIO48 | SPI SCLK | SPI MISO | SPI MOSI | I2C0 SCL | I2C0 SDA | UART0_TX_ | UART0_RX_ | PM_UART_TX | PM_UART_RX | UART0_TX | UART0_RX | AMIC- | AMIC+ | Purple Pi | R1 LTS
Ref Des/Silkscreen Top: RST | IDO-SBC2D06-V2A
XSECTION_CHART: *  SURFACE - AIR 0 MIL | L1: TOP CONDUCTOR - COPPER 1.2 MIL | *  DIELECTRIC - FR-4 8 MIL | L2: BOTTOM CONDUCTOR - COPPER 1.2 MIL | DESIGN CROSS SECTION CHART | ___________________________ | TOTAL THICKNESS 10.4 MIL | 1-2
DEVICE_TYPE_BOTTOM: FIGURE | SIZE | 11.811 | 20.0 | 27.559 | 31.496 | 32.0 | 36.0 | 39.37 | 40.0 | 71.0 | 118.11 | 47.201 | 127.949 | 48.0x20.0 | 66.929x43.311 | 74.799x24.409 | DRILL CHART: TOP to BOTTOM | ALL UNITS ARE IN MILS | PLATED | NON-PLATED | QTY | 674 | 2 | 6 | 4 | 24 | 40 | 1
